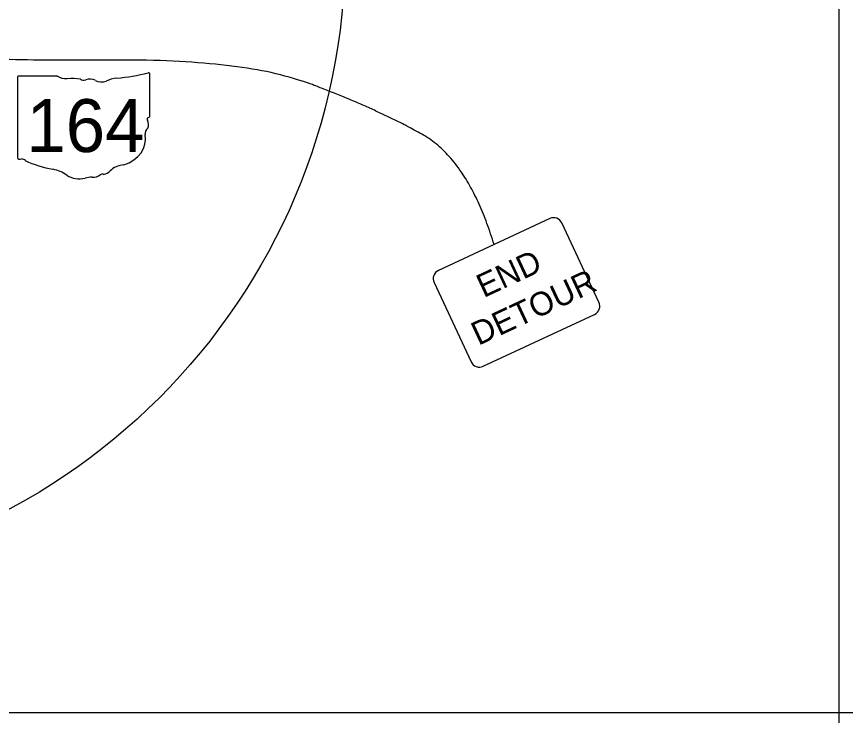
# Model space of a CAD drawing. Extents: x -740 to 1519, y 0 to 440.
# Drawn here: x 233.4 to 350.9, y 219.6 to 318.7 of the extents above; entities that cross this region are included whole.
import ezdxf

# ---------------------------------------------------------------- set-up
doc = ezdxf.new("R2010")
doc.units = 0
for name, color, linetype in [('GM_X_County_Road_Text', 7, 'Continuous'), ('GM_X_Minor_River', 7, 'Continuous'), ('GM_X_Section', 7, 'Continuous'), ('SH_Data', 7, 'Continuous')]:
    doc.layers.add(name, color=color, linetype=linetype)

msp = doc.modelspace()

# ---------------------------------------------------------------- linework, layer by layer
at = {"layer": 'GM_X_County_Road_Text'}
for p, q in [((239.24, 310.27), (233.75, 310.27)), ((252.31, 304.59), (252.31, 310.55)), ((233.56, 310.07), (233.56, 298.69)), ((252.31, 304.59), (252.31, 304.59))]:
    msp.add_line(p, q, dxfattribs=at)
for centre, major_axis, start_param, end_param in [((233.78, 310.09), (0.217, 0), 1.712693, 3.28349), ((240.55, 311.59), (2.11, 0), 4.042523, 4.731795), ((245.63, 325.79), (19.88, 0), 4.814394, 5.042369), ((252.11, 310.57), (0.209, 0), 6.141152, 7.989035), ((241.25, 303.87), (7.56, 0), 1.404758, 1.657858), ((242.96, 310.15), (0.608, 0), 3.836095, 5.185415), ((243.86, 308.84), (1.26, 0), 0.950623, 2.079405), ((245.49, 310.64), (1.52, 0), 4.081561, 5.145723), ((248.17, 306.79), (4, 0), 1.699011, 2.107814), ((252.27, 304.16), (0.323, 0), 1.883978, 3.671073), ((252.09, 304.57), (0.223, 0), 5.05454, 6.418171), ((250.21, 303.4), (1.94, 0), 5.934695, 6.695948), ((246.75, 301.34), (4.97, 0), 5.101752, 6.440018), ((253.06, 302.1), (1.41, 0), 2.387724, 3.262537), ((233.78, 298.66), (0.219, 0), 3.00124, 4.508301), ((233.81, 299.83), (1.67, 0), 4.665946, 4.897461), ((234.16, 298.03), (0.603, 0), 0.519207, 1.627899), ((241.77, 308.26), (14.36, 0), 4.195997, 4.488961), ((248.85, 295.49), (2.72, 0), 1.647645, 2.488434), ((237.49, 293.57), (4.49, 0), 0.823519, 1.323587), ((242.35, 297.97), (2.85, 0), 4.026481, 4.996735), ((244.2, 297.12), (1.52, 0), 4.691044, 5.507374), ((245.58, 296.02), (0.428, 0), 1.147584, 2.315152), ((245.39, 297.58), (1.61, 0), 4.937069, 5.64225), ((243.99, 294.04), (2.34, 0), 1.495662, 1.94098)]:
    msp.add_ellipse(centre, major_axis=major_axis, ratio=0.8, start_param=start_param, end_param=end_param, dxfattribs=at)
at = {"layer": 'GM_X_Minor_River'}
for points in [[(309, 290.06), (293.23, 282.7)], [(315.97, 278.2), (310.73, 289.43)], [(292.6, 280.97), (297.85, 269.74)], [(299.58, 269.11), (315.34, 276.47)]]:
    msp.add_lwpolyline(points, dxfattribs=at)
for centre, start, end in [((309.55, 288.88), 25.0288, 115.0288), ((293.78, 281.52), 115.0288, 205.0288), ((314.79, 277.65), 295.0288, 25.0288), ((299.03, 270.29), 205.0288, 295.0288)]:
    msp.add_arc(centre, 1.3, start, end, dxfattribs=at)
at = {"layer": 'GM_X_Section'}
for p, q in [((350, 10), (350, 430)), ((30, 220), (640, 220))]:
    msp.add_line(p, q, dxfattribs=at)
at = {"layer": 'SH_Data'}
msp.add_circle((190, 328.25), 90, dxfattribs=at)
msp.add_open_spline([(301.11, 286.38), (297.47, 298.35), (284.27, 305.71), (265.34, 312.77), (224.97, 312.3), (209.77, 315.51), (196.1, 322.76)], degree=2, dxfattribs=at)

# ---------------------------------------------------------------- texts
at = {"layer": 'GM_X_County_Road_Text'}
msp.add_text('164', height=7.5, dxfattribs=at).set_placement((234.83, 299.49))
at = {"layer": 'GM_X_Minor_River'}
for s, p in [('END', (299.63, 278.77)), ('DETOUR', (298.89, 272))]:
    msp.add_text(s, height=3.333, rotation=25.0288, dxfattribs=at).set_placement(p)

doc.saveas('drawing.dxf')
